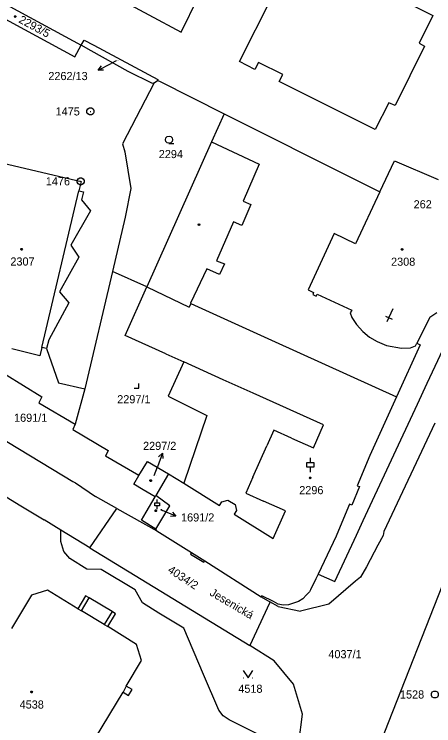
# Model space of a CAD drawing. Extents: x -528274 to -527531, y -1079304 to -1078580.
# Drawn here: x -527761.6 to -527673.9, y -1079170.6 to -1079021.9 of the extents above; entities that cross this region are included whole.
import ezdxf

# ---------------------------------------------------------------- set-up
doc = ezdxf.new("R2010")
doc.units = 0
doc.layers.add('katastrální mapa', color=7, linetype='Continuous')

msp = doc.modelspace()

# ---------------------------------------------------------------- linework, layer by layer
at = {"layer": 'katastrální mapa'}
for p, q in [((-527726.73, -1079025.62), (-527716.22, -1079004.12)), ((-527714.53, -1079031.8), (-527702.6, -1079007.97)), ((-527702.6, -1079007.97), (-527674.09, -1079022.13)), ((-527741.73, -1079017.56), (-527726.73, -1079025.62)), ((-527764.2, -1079019.38), (-527747.63, -1079028.38)), ((-527765.52, -1079021.81), (-527748.93, -1079030.76)), ((-527674.09, -1079022.13), (-527676.95, -1079027.92)), ((-527747.63, -1079028.38), (-527747.03, -1079027.28)), ((-527747.03, -1079027.28), (-527744.96, -1079028.38)), ((-527748.93, -1079030.76), (-527747.63, -1079028.38)), ((-527745.54, -1079029.51), (-527747.63, -1079028.38)), ((-527744.96, -1079028.38), (-527731.59, -1079035.52)), ((-527675.85, -1079028.53), (-527681.99, -1079040.96)), ((-527676.95, -1079027.92), (-527675.85, -1079028.53)), ((-527737.8, -1079033.88), (-527745.54, -1079029.51)), ((-527744.05, -1079033.6), (-527741.39, -1079032.21)), ((-527740.28, -1079031.63), (-527741.39, -1079032.21)), ((-527711.29, -1079033.42), (-527714.53, -1079031.8)), ((-527710.54, -1079031.98), (-527711.29, -1079033.42)), ((-527705.5, -1079034.45), (-527710.54, -1079031.98)), ((-527732.72, -1079036.36), (-527737.8, -1079033.88)), ((-527706.21, -1079035.95), (-527705.5, -1079034.45)), ((-527732.38, -1079036.24), (-527738.99, -1079048.94)), ((-527732.38, -1079036.24), (-527732.72, -1079036.36)), ((-527732.38, -1079036.24), (-527731.65, -1079035.71)), ((-527731.59, -1079035.52), (-527731.65, -1079035.71)), ((-527731.65, -1079035.71), (-527731.28, -1079035.9)), ((-527731.28, -1079035.9), (-527717.71, -1079042.69)), ((-527686.15, -1079045.96), (-527706.21, -1079035.95)), ((-527683.33, -1079040.38), (-527686.15, -1079045.96)), ((-527681.99, -1079040.96), (-527683.33, -1079040.38)), ((-527745.73, -1079042.19), (-527745.63, -1079042.19)), ((-527717.71, -1079042.69), (-527720.37, -1079048.58)), ((-527717.71, -1079042.69), (-527689.52, -1079056.81)), ((-527720.37, -1079048.58), (-527733.88, -1079078.84)), ((-527720.37, -1079048.58), (-527710.44, -1079053.2)), ((-527738.99, -1079048.94), (-527738.52, -1079050.61)), ((-527738.52, -1079050.61), (-527737.23, -1079058.33)), ((-527766.54, -1079052.38), (-527747.66, -1079056.84)), ((-527685.16, -1079059), (-527682.12, -1079052.54)), ((-527682.12, -1079052.54), (-527673.02, -1079056.4)), ((-527710.44, -1079053.2), (-527713.74, -1079060.98)), ((-527747.66, -1079056.84), (-527748.12, -1079058.79)), ((-527747.78, -1079056.79), (-527747.68, -1079056.79)), ((-527689.52, -1079056.81), (-527685.16, -1079059)), ((-527755.88, -1079091.51), (-527748.12, -1079058.79)), ((-527748.12, -1079058.79), (-527747.17, -1079059.01)), ((-527747.17, -1079059.01), (-527747.57, -1079060.68)), ((-527737.23, -1079058.33), (-527738.43, -1079064.27)), ((-527685.16, -1079059), (-527690.28, -1079069.87)), ((-527747.57, -1079060.68), (-527745.71, -1079062.98)), ((-527712.18, -1079061.65), (-527714.06, -1079066)), ((-527713.74, -1079060.98), (-527712.18, -1079061.65)), ((-527745.71, -1079062.98), (-527749.8, -1079070.17)), ((-527675.28, -1079098.98), (-527658.42, -1079062.82)), ((-527738.43, -1079064.27), (-527741.07, -1079075.61)), ((-527715.8, -1079065.24), (-527719.31, -1079073.39)), ((-527714.06, -1079066), (-527715.8, -1079065.24)), ((-527694.71, -1079067.7), (-527700.18, -1079079.48)), ((-527690.28, -1079069.87), (-527694.71, -1079067.7)), ((-527749.8, -1079070.17), (-527748.14, -1079072.62)), ((-527748.14, -1079072.62), (-527752.13, -1079079.86)), ((-527719.31, -1079073.39), (-527717.68, -1079074.03)), ((-527721.34, -1079075.09), (-527724.79, -1079082.27)), ((-527718.71, -1079076.24), (-527721.34, -1079075.09)), ((-527717.68, -1079074.03), (-527718.71, -1079076.24)), ((-527741.07, -1079075.61), (-527746.85, -1079100.14)), ((-527733.88, -1079078.84), (-527741.07, -1079075.61)), ((-527738.42, -1079089.02), (-527733.88, -1079078.84)), ((-527733.88, -1079078.84), (-527725.07, -1079083.08)), ((-527700.18, -1079079.48), (-527699.03, -1079080.01)), ((-527752.13, -1079079.86), (-527750.21, -1079082.17)), ((-527699.03, -1079080.01), (-527699.23, -1079080.46)), ((-527699.23, -1079080.46), (-527698.47, -1079080.81)), ((-527698.47, -1079080.81), (-527698.27, -1079080.37)), ((-527698.27, -1079080.37), (-527691.07, -1079083.71)), ((-527750.21, -1079082.17), (-527754.37, -1079089.89)), ((-527724.69, -1079082.32), (-527725.07, -1079083.08)), ((-527724.79, -1079082.27), (-527724.69, -1079082.32)), ((-527724.69, -1079082.32), (-527707.08, -1079090.32)), ((-527691.07, -1079083.71), (-527691.37, -1079084.25)), ((-527691.37, -1079084.25), (-527691.02, -1079085.23)), ((-527682.46, -1079083.47), (-527683.73, -1079086.19)), ((-527673.28, -1079084.26), (-527674.76, -1079085.26)), ((-527691.02, -1079085.23), (-527690.1, -1079086.68)), ((-527683.99, -1079084.96), (-527682.63, -1079085.6)), ((-527674.76, -1079085.26), (-527677.47, -1079090.59)), ((-527690.1, -1079086.68), (-527688.78, -1079088.17)), ((-527688.78, -1079088.17), (-527687.33, -1079089.34)), ((-527754.37, -1079089.89), (-527754.89, -1079091.74)), ((-527729.94, -1079092.84), (-527738.42, -1079089.02)), ((-527687.33, -1079089.34), (-527685.76, -1079090.24)), ((-527755.88, -1079091.51), (-527756.29, -1079093.24)), ((-527754.89, -1079091.74), (-527755.88, -1079091.51)), ((-527707.08, -1079090.32), (-527681.74, -1079101.82)), ((-527685.76, -1079090.24), (-527683.81, -1079091.07)), ((-527683.81, -1079091.07), (-527680.64, -1079091.65)), ((-527676.74, -1079090.96), (-527681.74, -1079101.82)), ((-527680.64, -1079091.65), (-527678.78, -1079091.58)), ((-527678.78, -1079091.58), (-527677.73, -1079091.14)), ((-527677.73, -1079091.14), (-527677.47, -1079090.59)), ((-527677.47, -1079090.59), (-527676.74, -1079090.96)), ((-527756.29, -1079093.24), (-527762.14, -1079091.81)), ((-527754.89, -1079091.74), (-527752.35, -1079098.88)), ((-527729.94, -1079092.84), (-527726.17, -1079094.54)), ((-527726.17, -1079094.54), (-527729.43, -1079101.67)), ((-527717.95, -1079098.24), (-527726.17, -1079094.54)), ((-527763.51, -1079097.06), (-527755.87, -1079101.8)), ((-527752.35, -1079098.88), (-527746.85, -1079100.14)), ((-527711.69, -1079101.06), (-527717.95, -1079098.24)), ((-527677.33, -1079103.36), (-527675.28, -1079098.98)), ((-527746.85, -1079100.14), (-527748.88, -1079107.56)), ((-527755.87, -1079101.8), (-527756.46, -1079103.05)), ((-527729.43, -1079101.67), (-527721.37, -1079105.71)), ((-527696.96, -1079107.7), (-527711.69, -1079101.06)), ((-527681.74, -1079101.82), (-527687.3, -1079114.07)), ((-527795.69, -1079103.27), (-527760.25, -1079124.58)), ((-527778.19, -1079102.14), (-527749.4, -1079119.49)), ((-527756.46, -1079103.05), (-527748.88, -1079107.56)), ((-527688.66, -1079127.66), (-527677.33, -1079103.36)), ((-527721.37, -1079105.71), (-527726.17, -1079119.89)), ((-527748.88, -1079107.56), (-527749.4, -1079108.62)), ((-527699.08, -1079112.47), (-527696.96, -1079107.7)), ((-527673.67, -1079107.35), (-527684.38, -1079129.98)), ((-527749.4, -1079108.62), (-527741.96, -1079113.01)), ((-527707.38, -1079108.82), (-527708.84, -1079112.08)), ((-527703.63, -1079110.47), (-527707.38, -1079108.82)), ((-527687.3, -1079179.85), (-527659.6, -1079109.31)), ((-527703.63, -1079110.47), (-527699.08, -1079112.47)), ((-527711.76, -1079118.62), (-527708.84, -1079112.08)), ((-527741.96, -1079113.01), (-527742.51, -1079114.19)), ((-527730.65, -1079113.63), (-527731.69, -1079116.44)), ((-527735.54, -1079118.25), (-527742.51, -1079114.19)), ((-527735.54, -1079118.25), (-527733.78, -1079115.37)), ((-527733.78, -1079115.37), (-527729.36, -1079117.92)), ((-527699.72, -1079115.54), (-527699.72, -1079114.54)), ((-527687.3, -1079114.07), (-527689.92, -1079120.39)), ((-527732.37, -1079118.26), (-527731.69, -1079116.44)), ((-527736.64, -1079120.04), (-527735.54, -1079118.25)), ((-527729.36, -1079117.92), (-527732.02, -1079122.47)), ((-527729.36, -1079117.92), (-527726.17, -1079119.89)), ((-527749.4, -1079119.49), (-527748.78, -1079119.77)), ((-527748.78, -1079119.77), (-527744.6, -1079122.67)), ((-527726.17, -1079119.89), (-527718.69, -1079124.51)), ((-527711.76, -1079118.62), (-527713.23, -1079121.92)), ((-527734.67, -1079121.23), (-527736.64, -1079120.04)), ((-527732.17, -1079122.73), (-527734.67, -1079121.23)), ((-527689.46, -1079120.58), (-527691.06, -1079124.44)), ((-527689.92, -1079120.39), (-527689.46, -1079120.58)), ((-527740.18, -1079125.15), (-527744.6, -1079122.67)), ((-527734.02, -1079125.89), (-527732.17, -1079122.73)), ((-527732.17, -1079122.73), (-527732.02, -1079122.47)), ((-527729.06, -1079124.63), (-527732.02, -1079122.47)), ((-527713.23, -1079121.92), (-527709.49, -1079123.6)), ((-527731.75, -1079123.96), (-527731.75, -1079123.29)), ((-527718.69, -1079124.51), (-527718.22, -1079123.75)), ((-527718.22, -1079123.75), (-527716.94, -1079123.43)), ((-527716.94, -1079123.43), (-527715.44, -1079124.34)), ((-527715.44, -1079124.34), (-527715.17, -1079125.59)), ((-527704.93, -1079125.65), (-527709.49, -1079123.6)), ((-527691.52, -1079124.25), (-527694.15, -1079130.58)), ((-527691.06, -1079124.44), (-527691.52, -1079124.25)), ((-527760.25, -1079124.58), (-527755.35, -1079127.53)), ((-527745.83, -1079133.38), (-527740.18, -1079125.15)), ((-527740.18, -1079125.15), (-527731.81, -1079129.83)), ((-527735.02, -1079127.59), (-527734.02, -1079125.89)), ((-527731.06, -1079125.38), (-527730.6, -1079125.58)), ((-527730.95, -1079127.73), (-527729.06, -1079124.63)), ((-527727.83, -1079126.74), (-527730.6, -1079125.58)), ((-527715.17, -1079125.59), (-527715.67, -1079126.37)), ((-527707.49, -1079131.42), (-527704.93, -1079125.65)), ((-527715.67, -1079126.37), (-527707.49, -1079131.42)), ((-527751.89, -1079129.66), (-527755.35, -1079127.53)), ((-527732.01, -1079129.46), (-527735.02, -1079127.59)), ((-527732.01, -1079129.46), (-527730.95, -1079127.73)), ((-527690.09, -1079130.72), (-527688.66, -1079127.66)), ((-527751.9, -1079132.08), (-527751.89, -1079129.66)), ((-527745.83, -1079133.38), (-527751.89, -1079129.66)), ((-527731.81, -1079129.83), (-527732.01, -1079129.46)), ((-527731.81, -1079129.83), (-527724.56, -1079134.33)), ((-527684.38, -1079129.98), (-527684.49, -1079130.83)), ((-527694.33, -1079130.96), (-527698.11, -1079138.85)), ((-527694.62, -1079140.43), (-527690.09, -1079130.72)), ((-527694.15, -1079130.58), (-527694.33, -1079130.96)), ((-527684.49, -1079130.83), (-527685.58, -1079132.84)), ((-527751.27, -1079134.11), (-527751.9, -1079132.08)), ((-527685.58, -1079132.84), (-527687.98, -1079137.32)), ((-527750.02, -1079135.62), (-527751.27, -1079134.11)), ((-527745.83, -1079133.38), (-527712.39, -1079153.8)), ((-527724.56, -1079134.33), (-527724.77, -1079134.67)), ((-527724.77, -1079134.67), (-527721.99, -1079136.36)), ((-527724.56, -1079134.33), (-527721.75, -1079136.11)), ((-527746.43, -1079137.81), (-527750.02, -1079135.62)), ((-527721.99, -1079136.36), (-527721.75, -1079136.11)), ((-527721.75, -1079136.11), (-527710.01, -1079143.62)), ((-527687.98, -1079137.32), (-527689.23, -1079139.48)), ((-527743.42, -1079137.9), (-527746.43, -1079137.81)), ((-527736.37, -1079142.18), (-527743.42, -1079137.9)), ((-527698.11, -1079138.85), (-527698.59, -1079139.86)), ((-527698.11, -1079138.85), (-527694.62, -1079140.43)), ((-527698.59, -1079139.86), (-527699.67, -1079142.13)), ((-527690.26, -1079140.36), (-527695.88, -1079145.17)), ((-527689.23, -1079139.48), (-527690.26, -1079140.36)), ((-527754.65, -1079142.25), (-527757.98, -1079143.23)), ((-527748.32, -1079146.1), (-527754.65, -1079142.25)), ((-527734.84, -1079144.88), (-527736.37, -1079142.18)), ((-527699.67, -1079142.13), (-527699.87, -1079142.54)), ((-527757.98, -1079143.23), (-527762.17, -1079150.21)), ((-527746.69, -1079143.39), (-527748.32, -1079146.1)), ((-527745.92, -1079143.85), (-527746.69, -1079143.39)), ((-527709.89, -1079143.43), (-527710.01, -1079143.62)), ((-527710.01, -1079143.62), (-527708.16, -1079144.66)), ((-527707.45, -1079144.58), (-527709.89, -1079143.43)), ((-527700.49, -1079143.22), (-527701.28, -1079144.03)), ((-527699.87, -1079142.54), (-527700.49, -1079143.22)), ((-527747.56, -1079146.55), (-527745.92, -1079143.85)), ((-527741.18, -1079146.71), (-527745.92, -1079143.85)), ((-527731.36, -1079147), (-527734.84, -1079144.88)), ((-527708.27, -1079144.91), (-527712.39, -1079153.8)), ((-527708.16, -1079144.66), (-527708.27, -1079144.91)), ((-527706.43, -1079145.64), (-527708.16, -1079144.66)), ((-527706.44, -1079145.11), (-527707.45, -1079144.58)), ((-527705.38, -1079145.33), (-527706.44, -1079145.11)), ((-527702.17, -1079144.61), (-527704.29, -1079145.31)), ((-527701.28, -1079144.03), (-527702.17, -1079144.61)), ((-527695.88, -1079145.17), (-527701.81, -1079146.64)), ((-527748.32, -1079146.1), (-527747.56, -1079146.55)), ((-527742.82, -1079149.37), (-527747.56, -1079146.55)), ((-527741.18, -1079146.71), (-527742.82, -1079149.37)), ((-527740.43, -1079147.16), (-527741.18, -1079146.71)), ((-527706.43, -1079145.64), (-527701.81, -1079146.64)), ((-527704.29, -1079145.31), (-527705.38, -1079145.33)), ((-527742.05, -1079149.83), (-527740.43, -1079147.16)), ((-527726.19, -1079150.15), (-527731.36, -1079147)), ((-527742.82, -1079149.37), (-527742.05, -1079149.83)), ((-527736.09, -1079153.54), (-527742.05, -1079149.83)), ((-527722.07, -1079159.87), (-527726.19, -1079150.15)), ((-527735, -1079156.92), (-527736.09, -1079153.54)), ((-527707.31, -1079156.97), (-527712.39, -1079153.8)), ((-527738.22, -1079162.26), (-527735, -1079156.92)), ((-527703.21, -1079161.88), (-527707.31, -1079156.97)), ((-527718.87, -1079167.28), (-527722.07, -1079159.87)), ((-527713.7, -1079160.51), (-527713.6, -1079160.51)), ((-527711.9, -1079160.51), (-527711.8, -1079160.51)), ((-527738.22, -1079162.26), (-527738.88, -1079163.5)), ((-527736.95, -1079162.95), (-527738.22, -1079162.26)), ((-527737.76, -1079164.22), (-527736.95, -1079162.95)), ((-527701.35, -1079168.12), (-527703.21, -1079161.88)), ((-527744.65, -1079173.08), (-527738.88, -1079163.5)), ((-527738.88, -1079163.5), (-527737.76, -1079164.22)), ((-527717.91, -1079168.46), (-527718.87, -1079167.28)), ((-527716.66, -1079169.32), (-527717.91, -1079168.46)), ((-527702.31, -1079175.73), (-527701.35, -1079168.12)), ((-527707.76, -1079173.77), (-527716.66, -1079169.32))]:
    msp.add_line(p, q, dxfattribs=at)
for points in [[(-527761.43, -1079022.2), (-527761.33, -1079022.22), (-527761.28, -1079022.31), (-527761.26, -1079022.37), (-527761.28, -1079022.46), (-527761.36, -1079022.53), (-527761.43, -1079022.54), (-527761.52, -1079022.51), (-527761.58, -1079022.45), (-527761.6, -1079022.37), (-527761.58, -1079022.28), (-527761.5, -1079022.21)], [(-527745.49, -1079041.47), (-527745.15, -1079041.66), (-527744.96, -1079042), (-527744.96, -1079042.39), (-527745.15, -1079042.73), (-527745.49, -1079042.92), (-527745.88, -1079042.92), (-527746.22, -1079042.73), (-527746.41, -1079042.39), (-527746.41, -1079042), (-527746.22, -1079041.66), (-527745.88, -1079041.47)], [(-527747.54, -1079056.07), (-527747.2, -1079056.26), (-527747.01, -1079056.6), (-527747.01, -1079056.99), (-527747.2, -1079057.33), (-527747.54, -1079057.52), (-527747.93, -1079057.52), (-527748.27, -1079057.33), (-527748.46, -1079056.99), (-527748.46, -1079056.6), (-527748.27, -1079056.26), (-527747.93, -1079056.07)], [(-527722.91, -1079065.7), (-527722.82, -1079065.85), (-527722.91, -1079066), (-527723.09, -1079066), (-527723.18, -1079065.85), (-527723.09, -1079065.7)], [(-527760.09, -1079070.82), (-527759.99, -1079070.84), (-527759.94, -1079070.93), (-527759.92, -1079070.99), (-527759.94, -1079071.08), (-527760.02, -1079071.15), (-527760.09, -1079071.16), (-527760.18, -1079071.13), (-527760.24, -1079071.07), (-527760.26, -1079070.99), (-527760.24, -1079070.9), (-527760.16, -1079070.83)], [(-527680.53, -1079070.85), (-527680.43, -1079070.87), (-527680.38, -1079070.96), (-527680.36, -1079071.02), (-527680.38, -1079071.11), (-527680.46, -1079071.18), (-527680.53, -1079071.19), (-527680.62, -1079071.16), (-527680.68, -1079071.1), (-527680.7, -1079071.02), (-527680.68, -1079070.93), (-527680.6, -1079070.86)], [(-527733.1, -1079119.16), (-527733, -1079119.18), (-527732.95, -1079119.27), (-527732.93, -1079119.33), (-527732.95, -1079119.42), (-527733.03, -1079119.49), (-527733.1, -1079119.5), (-527733.19, -1079119.47), (-527733.25, -1079119.41), (-527733.27, -1079119.33), (-527733.25, -1079119.24), (-527733.17, -1079119.17)], [(-527699.76, -1079118.59), (-527699.66, -1079118.61), (-527699.61, -1079118.7), (-527699.59, -1079118.76), (-527699.61, -1079118.85), (-527699.69, -1079118.92), (-527699.76, -1079118.93), (-527699.85, -1079118.9), (-527699.91, -1079118.84), (-527699.93, -1079118.76), (-527699.91, -1079118.67), (-527699.83, -1079118.6)], [(-527732.04, -1079125.45), (-527731.94, -1079125.47), (-527731.89, -1079125.56), (-527731.87, -1079125.62), (-527731.89, -1079125.71), (-527731.97, -1079125.78), (-527732.04, -1079125.79), (-527732.13, -1079125.76), (-527732.19, -1079125.7), (-527732.21, -1079125.62), (-527732.19, -1079125.53), (-527732.11, -1079125.46)], [(-527758, -1079163.32), (-527757.9, -1079163.34), (-527757.85, -1079163.43), (-527757.83, -1079163.49), (-527757.85, -1079163.58), (-527757.93, -1079163.65), (-527758, -1079163.66), (-527758.09, -1079163.63), (-527758.15, -1079163.57), (-527758.17, -1079163.49), (-527758.15, -1079163.4), (-527758.07, -1079163.33)], [(-527673.5, -1079163.29), (-527673.16, -1079163.48), (-527672.97, -1079163.82), (-527672.97, -1079164.21), (-527673.16, -1079164.55), (-527673.5, -1079164.74), (-527673.89, -1079164.74), (-527674.23, -1079164.55), (-527674.42, -1079164.21), (-527674.42, -1079163.82), (-527674.23, -1079163.48), (-527673.89, -1079163.29)]]:
    msp.add_lwpolyline(points, close=True, dxfattribs=at)
for points in [[(-527742.93, -1079033.58), (-527744.05, -1079033.6), (-527743.39, -1079032.69)], [(-527729.25, -1079048.85), (-527729.63, -1079048.75), (-527729.9, -1079048.48), (-527730, -1079048.11), (-527729.9, -1079047.74), (-527729.63, -1079047.47), (-527729.26, -1079047.37), (-527728.89, -1079047.47), (-527728.62, -1079047.74), (-527728.52, -1079048.12), (-527728.62, -1079048.5), (-527728.89, -1079048.77), (-527729.27, -1079048.87), (-527728.27, -1079048.87)], [(-527736.57, -1079100.03), (-527735.57, -1079100.03), (-527735.57, -1079099.03)], [(-527731.46, -1079114.39), (-527730.65, -1079113.63), (-527730.53, -1079114.74)], [(-527699.72, -1079117.54), (-527699.72, -1079116.54), (-527700.47, -1079116.54), (-527700.47, -1079115.54), (-527699.72, -1079115.54), (-527698.97, -1079115.54), (-527698.97, -1079116.54), (-527699.72, -1079116.54)], [(-527731.75, -1079125.3), (-527731.75, -1079124.63), (-527732.25, -1079124.63), (-527732.25, -1079123.96), (-527731.75, -1079123.96), (-527731.25, -1079123.96), (-527731.25, -1079124.63), (-527731.75, -1079124.63)], [(-527728.56, -1079125.89), (-527727.83, -1079126.74), (-527728.95, -1079126.81)], [(-527713.75, -1079159.01), (-527712.75, -1079160.51), (-527711.75, -1079159.01)]]:
    msp.add_lwpolyline(points, dxfattribs=at)

# ---------------------------------------------------------------- texts
for s, rotation, p in [('2293/5', 331.5134, (-527760.83, -1079023.53)), ('4034/2', 327.0443, (-527729.68, -1079138.38)), ('Jesenická', 329.2788, (-527720.9, -1079143.19))]:
    msp.add_text(s, height=1.7, rotation=rotation, dxfattribs=at).set_placement(p)
for s, height, p in [('2262/13', 0.1, (-527740.27, -1079031.63)), ('2262/13', 1.7, (-527754.49, -1079035.65)), ('1475', 1.7, (-527752.97, -1079043.04)), ('2294', 1.7, (-527731.4, -1079051.95)), ('1476', 1.7, (-527755.02, -1079057.64)), ('262', 1.7, (-527678.13, -1079062.45)), ('2307', 1.7, (-527762.42, -1079074.4)), ('2308', 1.7, (-527682.84, -1079074.44)), ('2297/1', 1.7, (-527740.09, -1079103.18)), ('1691/1', 1.7, (-527761.66, -1079107.04)), ('2297/2', 1.7, (-527734.69, -1079112.92)), ('2297/2', 0.1, (-527732.36, -1079118.26)), ('2296', 1.7, (-527702.04, -1079122.17)), ('1691/2', 0.1, (-527731.04, -1079125.38)), ('1691/2', 1.7, (-527726.75, -1079127.87)), ('4037/1', 1.7, (-527695.95, -1079156.44)), ('4518', 1.7, (-527714.78, -1079163.66)), ('1528', 1.7, (-527680.98, -1079164.86)), ('4538', 1.7, (-527760.49, -1079166.96))]:
    msp.add_text(s, height=height, dxfattribs=at).set_placement(p)

doc.saveas('drawing.dxf')
